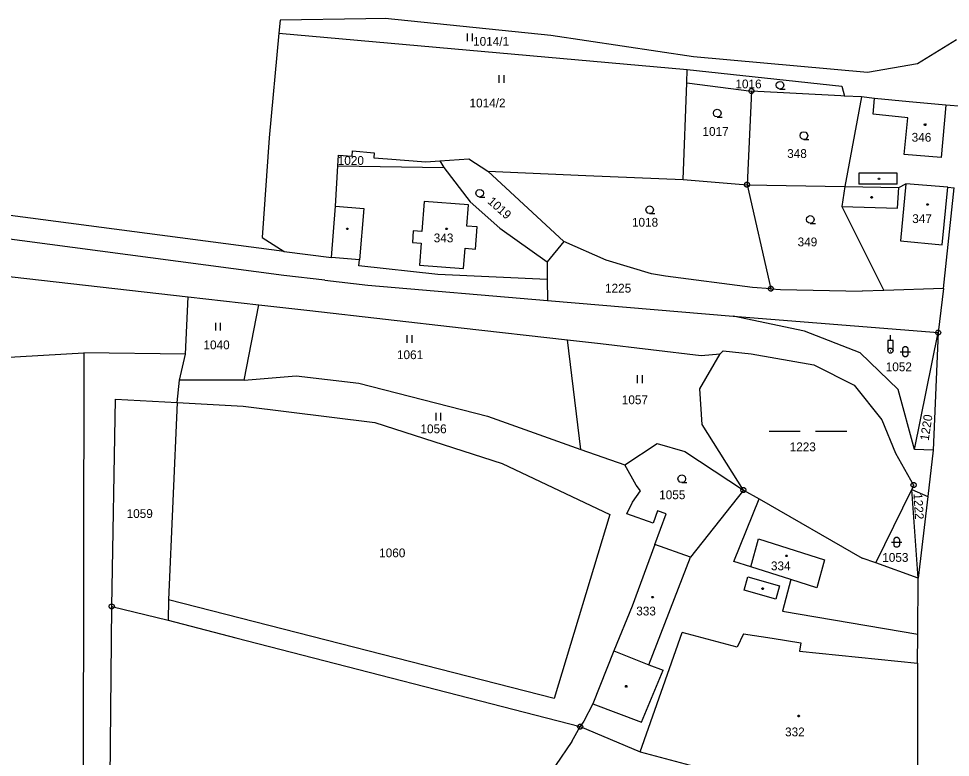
# Model space of a CAD drawing. Extents: x -812394 to -807601, y -1013098 to -1009266.
# Drawn here: x -811185.3 to -811005.4, y -1011290.4 to -1011147.8 of the extents above; entities that cross this region are included whole.
import ezdxf

# ---------------------------------------------------------------- set-up
doc = ezdxf.new("R2010")
doc.units = 0
for name, color, linetype in [('KN_HRANICE', 7, 'Continuous'), ('KN_KULTURY', 7, 'Continuous'), ('KN_MEZNIKY', 7, 'Continuous'), ('KN_PARCELY', 7, 'Continuous'), ('KN_SLUCKY', 7, 'Continuous'), ('KN_VEDENI', 7, 'Continuous')]:
    doc.layers.add(name, color=color, linetype=linetype)

# ---------------------------------------------------------------- blocks, each defined once
blk = doc.blocks.new('304')
blk.add_lwpolyline([(0, 0), (-0.38, 0.1), (-0.65, 0.37), (-0.75, 0.74), (-0.65, 1.11), (-0.38, 1.38), (-0.01, 1.48), (0.36, 1.38), (0.63, 1.11), (0.73, 0.73), (0.63, 0.35), (0.36, 0.08), (-0.02, -0.02), (0.98, -0.02)])
blk = doc.blocks.new('306')
for p, q in [((-0.5, 1.5), (-0.5, 0)), ((0.5, 0), (0.5, 1.5))]:
    blk.add_line(p, q)
blk = doc.blocks.new('316')
for points in [[(-0.5, 1.5), (-0.4, 1.79), (-0.15, 1.97), (0.16, 1.97), (0.41, 1.79), (0.51, 1.5), (0.51, 0.5), (0.41, 0.21), (0.16, 0.03), (-0.15, 0.03), (-0.4, 0.21), (-0.5, 0.5), (-0.5, 1.5)], [(-1, 1), (0.27, 1), (1, 1)]]:
    blk.add_lwpolyline(points)
blk = doc.blocks.new('NAHRADNI_SYMBOL')
blk.add_lwpolyline([(0.09, 0.15), (0.18, 0), (0.09, -0.15), (-0.09, -0.15), (-0.18, 0), (-0.09, 0.15), (0.09, 0.15)])
blk = doc.blocks.new('803')
for p, q in [((-7.5, 0), (-1.5, 0)), ((1.5, 0), (7.5, 0))]:
    blk.add_line(p, q)
blk = doc.blocks.new('402')
blk.add_lwpolyline([(0.09, 0.15), (0.18, 0), (0.09, -0.15), (-0.09, -0.15), (-0.18, 0), (-0.09, 0.15), (0.09, 0.15)])
blk = doc.blocks.new('105')
blk.add_line((-0.12, 0), (0.12, 0))
blk.add_lwpolyline([(0.15, 0.48), (0.4, 0.3), (0.5, 0.01), (0.4, -0.28), (0.15, -0.46), (-0.16, -0.46), (-0.41, -0.28), (-0.51, 0.01), (-0.41, 0.3), (-0.16, 0.48), (0.15, 0.48)])
blk = doc.blocks.new('4112')
for p, q in [((0, 2), (0, 3)), ((-0.05, 0), (0.05, 0))]:
    blk.add_line(p, q)
for points in [[(0.5, 0), (0.4, -0.29), (0.15, -0.47), (-0.16, -0.47), (-0.41, -0.29), (-0.51, 0), (-0.41, 0.29), (-0.16, 0.47), (0.15, 0.47), (0.4, 0.29), (0.5, 0), (0.5, 1.27), (0.5, 2), (0, 2), (-0.5, 2), (-0.5, 0.73), (-0.5, 0)], [(-0.05, 0), (0, 0), (0.05, 0)]]:
    blk.add_lwpolyline(points)

msp = doc.modelspace()

# ---------------------------------------------------------------- linework, layer by layer
at = {"layer": 'KN_HRANICE'}
for p, q in [((-811114.53, -1011147.8), (-811118.29, -1011147.86)), ((-811082.55, -1011151.04), (-811114.53, -1011147.8)), ((-811135.05, -1011150.61), (-811056.18, -1011157.62)), ((-811055, -1011155.17), (-811082.55, -1011151.04)), ((-811004.2, -1011151.86), (-811011.7, -1011156.55)), ((-811021.36, -1011158.23), (-811055, -1011155.17)), ((-811011.7, -1011156.55), (-811021.36, -1011158.23)), ((-811056.28, -1011160.19), (-811056.18, -1011157.62)), ((-811056.99, -1011178.87), (-811056.28, -1011160.19)), ((-811056.28, -1011160.19), (-811043.79, -1011161.8)), ((-811043.79, -1011161.8), (-811044.65, -1011179.88)), ((-811026.5, -1011162.71), (-811043.79, -1011161.8)), ((-811025.83, -1011162.74), (-811026.5, -1011162.71)), ((-811022.54, -1011162.91), (-811025.83, -1011162.74)), ((-811022.54, -1011162.91), (-811025.73, -1011180.21)), ((-811020, -1011163.23), (-811022.54, -1011162.91)), ((-811013.31, -1011163.87), (-811020, -1011163.23)), ((-811006.28, -1011164.5), (-811013.31, -1011163.87)), ((-811002.95, -1011164.79), (-811006.28, -1011164.5)), ((-811124.13, -1011184), (-811123.68, -1011176.2)), ((-811123.68, -1011176.2), (-811103.23, -1011176.54)), ((-811103.94, -1011175.27), (-811098.37, -1011174.88)), ((-811103.94, -1011175.27), (-811103.23, -1011176.54)), ((-811098.37, -1011174.88), (-811094.68, -1011177.27)), ((-811080.02, -1011190.85), (-811094.68, -1011177.27)), ((-811056.99, -1011178.87), (-811044.65, -1011179.88)), ((-811044.65, -1011179.88), (-811025.73, -1011180.21)), ((-811044.65, -1011179.88), (-811040.04, -1011199.96)), ((-811015.31, -1011180.39), (-811013.97, -1011179.67)), ((-811005.89, -1011180.37), (-811013.97, -1011179.67)), ((-811025.73, -1011180.21), (-811026.32, -1011184.09)), ((-811025.73, -1011180.21), (-811015.31, -1011180.39)), ((-811006.73, -1011199.88), (-811004.64, -1011180.47)), ((-811005.89, -1011180.37), (-811004.64, -1011180.47)), ((-811134.04, -1011192.78), (-811204.59, -1011183.52)), ((-811124.88, -1011193.92), (-811124.13, -1011184)), ((-811026.32, -1011184.09), (-811018.25, -1011200.3)), ((-811080.02, -1011190.85), (-811083.26, -1011194.74)), ((-811134.04, -1011192.78), (-811124.88, -1011193.92)), ((-811119.51, -1011194.4), (-811124.88, -1011193.92)), ((-811119.59, -1011195.52), (-811119.51, -1011194.4)), ((-811210.26, -1011194.98), (-811152.56, -1011201.49)), ((-811083.26, -1011194.74), (-811083.23, -1011198.18)), ((-811126.17, -1011198.3), (-811117.85, -1011199.26)), ((-811117.85, -1011199.26), (-811083.19, -1011202.2)), ((-811083.23, -1011198.18), (-811083.19, -1011202.2)), ((-811153.06, -1011212.61), (-811152.56, -1011201.49)), ((-811152.56, -1011201.49), (-811138.94, -1011203.04)), ((-811040.04, -1011199.96), (-811038.15, -1011200.07)), ((-811038.15, -1011200.07), (-811022.4, -1011200.45)), ((-811018.25, -1011200.3), (-811022.4, -1011200.45)), ((-811006.73, -1011199.88), (-811018.25, -1011200.3)), ((-811006.73, -1011199.88), (-811007.74, -1011208.42)), ((-811141.76, -1011217.63), (-811138.94, -1011203.04)), ((-811138.94, -1011203.04), (-811129.08, -1011204.17)), ((-811083.19, -1011202.2), (-811047.34, -1011205.25)), ((-811129.08, -1011204.17), (-811099.83, -1011207.51)), ((-811047.34, -1011205.25), (-811007.74, -1011208.42)), ((-811099.83, -1011207.51), (-811079.29, -1011209.81)), ((-811012.31, -1011230.97), (-811007.74, -1011208.42)), ((-811007.74, -1011208.42), (-811008.72, -1011231.09)), ((-811076.71, -1011230.96), (-811079.29, -1011209.81)), ((-811192.07, -1011213.48), (-811172.71, -1011212.32)), ((-811172.71, -1011212.32), (-811172.89, -1011326.55)), ((-811153.06, -1011212.61), (-811172.71, -1011212.32)), ((-811154.23, -1011217.6), (-811153.06, -1011212.61)), ((-811154.72, -1011221.9), (-811154.23, -1011217.6)), ((-811141.76, -1011217.63), (-811154.23, -1011217.6)), ((-811167.33, -1011261.3), (-811166.6, -1011221.24)), ((-811166.6, -1011221.24), (-811154.72, -1011221.9)), ((-811154.72, -1011221.9), (-811156.36, -1011260.04)), ((-811154.72, -1011221.9), (-811141.93, -1011222.61)), ((-811141.93, -1011222.61), (-811116.52, -1011225.79)), ((-811116.52, -1011225.79), (-811091.96, -1011233.67)), ((-811076.71, -1011230.96), (-811068.27, -1011233.96)), ((-811008.72, -1011231.09), (-811012.31, -1011230.97)), ((-811008.72, -1011231.09), (-811009.72, -1011240.09)), ((-811091.96, -1011233.67), (-811071.16, -1011243.55)), ((-811045.35, -1011238.81), (-811055.55, -1011251.77)), ((-811045.35, -1011238.81), (-811042.32, -1011240.54)), ((-811019.74, -1011252.9), (-811012.81, -1011238.74)), ((-811012.81, -1011238.74), (-811009.72, -1011240.09)), ((-811011.6, -1011255.83), (-811012.81, -1011238.74)), ((-811047.2, -1011252.6), (-811042.32, -1011240.54)), ((-811042.32, -1011240.54), (-811022.4, -1011251.94)), ((-811009.72, -1011240.09), (-811011.6, -1011255.83)), ((-811071.16, -1011243.55), (-811081.9, -1011279.06)), ((-811062.44, -1011249.35), (-811066.83, -1011261.23)), ((-811055.55, -1011251.77), (-811062.44, -1011249.35)), ((-811019.74, -1011252.9), (-811022.4, -1011251.94)), ((-811043.88, -1011253.66), (-811047.2, -1011252.6)), ((-811036.19, -1011256.11), (-811043.88, -1011253.66)), ((-811011.6, -1011255.83), (-811019.74, -1011252.9)), ((-811036.19, -1011256.11), (-811037.78, -1011262.21)), ((-811011.67, -1011266.63), (-811011.6, -1011255.83)), ((-811156.36, -1011260.04), (-811156.44, -1011263.96)), ((-811081.9, -1011279.06), (-811156.36, -1011260.04)), ((-811167.89, -1011326.74), (-811167.33, -1011261.3)), ((-811167.33, -1011261.3), (-811156.44, -1011263.96)), ((-811066.83, -1011261.23), (-811070.36, -1011269.87)), ((-811037.78, -1011262.21), (-811011.67, -1011266.63)), ((-811156.44, -1011263.96), (-811143.37, -1011267.37)), ((-811065.28, -1011289.37), (-811057.2, -1011266.35)), ((-811046.57, -1011269.18), (-811057.2, -1011266.35)), ((-811143.37, -1011267.37), (-811076.86, -1011284.5)), ((-811045.32, -1011266.57), (-811046.57, -1011269.18)), ((-811045.32, -1011266.57), (-811039.78, -1011267.43)), ((-811039.78, -1011267.43), (-811034.25, -1011268.29)), ((-811011.7, -1011272.27), (-811011.67, -1011266.63)), ((-811070.36, -1011269.87), (-811074.4, -1011280.09)), ((-811034.25, -1011268.29), (-811034.51, -1011269.93)), ((-811034.51, -1011269.93), (-811011.7, -1011272.27)), ((-811011.7, -1011272.27), (-811011.75, -1011293.77)), ((-811074.4, -1011280.09), (-811076.18, -1011283.43)), ((-811076.18, -1011283.43), (-811076.86, -1011284.5)), ((-811078.49, -1011287.34), (-811076.86, -1011284.5)), ((-811076.86, -1011284.5), (-811065.28, -1011289.37)), ((-811078.49, -1011287.34), (-811081.65, -1011291.97)), ((-811065.28, -1011289.37), (-811054.65, -1011292.2))]:
    msp.add_line(p, q, dxfattribs=at)
for points in [[(-811118.29, -1011147.86), (-811134.82, -1011148.12), (-811135.05, -1011150.61)], [(-811135.05, -1011150.61), (-811136.91, -1011170.79), (-811138.29, -1011190.03), (-811134.04, -1011192.78)], [(-811056.18, -1011157.62), (-811026.31, -1011160.81), (-811025.83, -1011162.74)], [(-811123.68, -1011176.2), (-811123.56, -1011174.16), (-811120.9, -1011174.34), (-811120.82, -1011173.33), (-811116.66, -1011173.68), (-811116.74, -1011174.67), (-811114.06, -1011174.87), (-811106.69, -1011175.46), (-811103.94, -1011175.27)], [(-811103.23, -1011176.54), (-811098.1, -1011183.16), (-811092.39, -1011188.27), (-811083.26, -1011194.74)], [(-811094.68, -1011177.27), (-811075.76, -1011178.11), (-811056.99, -1011178.87)], [(-811126.17, -1011198.3), (-811134.07, -1011197.39), (-811205.09, -1011188), (-811235.6, -1011185.13), (-811253.42, -1011185.08)], [(-811040.04, -1011199.96), (-811043.56, -1011199.74), (-811060.37, -1011197.53), (-811063.11, -1011197.07), (-811071.87, -1011194.45), (-811080.02, -1011190.85)], [(-811083.23, -1011198.18), (-811104.34, -1011197.21), (-811119.59, -1011195.52)], [(-811012.31, -1011230.97), (-811015.45, -1011219.39), (-811022.8, -1011212.32), (-811033.57, -1011208.12), (-811047.34, -1011205.25)], [(-811079.29, -1011209.81), (-811072.96, -1011210.52), (-811053.49, -1011212.84), (-811049.84, -1011212.52)], [(-811049.84, -1011212.52), (-811049.25, -1011211.91), (-811043.85, -1011212.49), (-811031.77, -1011214.67), (-811023.94, -1011218.57), (-811018.6, -1011225.28), (-811016, -1011231.72), (-811012.47, -1011237.86), (-811012.81, -1011238.74)], [(-811045.35, -1011238.81), (-811053.28, -1011226.18), (-811053.74, -1011219.25), (-811049.84, -1011212.52)], [(-811141.76, -1011217.63), (-811131.69, -1011216.74), (-811119.6, -1011218.21), (-811094.76, -1011224.53), (-811076.71, -1011230.96)], [(-811068.27, -1011233.96), (-811061.97, -1011229.86), (-811056.63, -1011231.35), (-811045.35, -1011238.81)], [(-811062.44, -1011249.35), (-811060.27, -1011243.4), (-811061.93, -1011242.85), (-811062.75, -1011245.19), (-811067.83, -1011243.42), (-811066.75, -1011241.18), (-811065.25, -1011238.95), (-811066.04, -1011237.88), (-811068.27, -1011233.96)]]:
    msp.add_lwpolyline(points, dxfattribs=at)
at = {"layer": 'KN_SLUCKY'}
for p, q in [((-811020.31, -1011166.25), (-811020, -1011163.23)), ((-811006.28, -1011164.5), (-811007.17, -1011174.62)), ((-811013.57, -1011166.94), (-811020.31, -1011166.25)), ((-811014.3, -1011174.03), (-811013.57, -1011166.94)), ((-811007.17, -1011174.62), (-811014.3, -1011174.03)), ((-811015.68, -1011177.63), (-811023.04, -1011177.63)), ((-811023.04, -1011177.63), (-811023.04, -1011179.74)), ((-811015.68, -1011179.74), (-811015.68, -1011177.63)), ((-811015.68, -1011179.74), (-811023.04, -1011179.74)), ((-811013.97, -1011179.67), (-811015.01, -1011190.72)), ((-811015.57, -1011184.38), (-811015.31, -1011180.39)), ((-811006.98, -1011191.46), (-811005.89, -1011180.37)), ((-811026.32, -1011184.09), (-811015.57, -1011184.38)), ((-811015.01, -1011190.72), (-811006.98, -1011191.46)), ((-811043.88, -1011253.66), (-811042.43, -1011248.25)), ((-811042.43, -1011248.25), (-811029.67, -1011252.31)), ((-811063.58, -1011272.55), (-811055.55, -1011251.77)), ((-811029.67, -1011252.31), (-811031.16, -1011257.72)), ((-811045.19, -1011258.17), (-811044.48, -1011255.6)), ((-811044.48, -1011255.6), (-811038.35, -1011257.29)), ((-811038.35, -1011257.29), (-811039.06, -1011259.86)), ((-811031.16, -1011257.72), (-811036.19, -1011256.11)), ((-811039.06, -1011259.86), (-811045.19, -1011258.17)), ((-811070.36, -1011269.87), (-811063.58, -1011272.55)), ((-811065.03, -1011283.62), (-811060.86, -1011273.62)), ((-811063.58, -1011272.55), (-811060.86, -1011273.62)), ((-811074.4, -1011280.09), (-811065.03, -1011283.62))]:
    msp.add_line(p, q, dxfattribs=at)
msp.add_lwpolyline([(-811107.44, -1011188.88), (-811109.09, -1011188.75), (-811109.27, -1011191.03), (-811107.56, -1011191.17), (-811107.89, -1011195.41), (-811099.4, -1011196.06), (-811099.09, -1011192.13), (-811097.08, -1011192.29), (-811096.74, -1011188.01), (-811098.74, -1011187.86), (-811098.41, -1011183.73), (-811106.99, -1011183.09)], close=True, dxfattribs=at)
msp.add_lwpolyline([(-811124.13, -1011184), (-811118.64, -1011184.45), (-811119.51, -1011194.4)], dxfattribs=at)

# ---------------------------------------------------------------- block references
at = {"layer": 'KN_KULTURY'}
for name, p in [('306', (-811098.18, -1011152.15)), ('306', (-811092.05, -1011160.21)), ('304', (-811038.28, -1011161.4)), ('304', (-811050.4, -1011166.78)), ('402', (-811010.26, -1011168.29)), ('304', (-811033.66, -1011171.12)), ('402', (-811019.17, -1011178.74)), ('304', (-811096.26, -1011182.24)), ('402', (-811020.57, -1011182.29)), ('402', (-811009.78, -1011183.68)), ('304', (-811063.44, -1011185.43)), ('304', (-811032.42, -1011187.31)), ('402', (-811121.83, -1011188.38)), ('402', (-811102.67, -1011188.38)), ('306', (-811146.8, -1011208.03)), ('306', (-811109.84, -1011210.39)), ('316', (-811014.08, -1011213.1)), ('306', (-811065.35, -1011218.16)), ('306', (-811104.25, -1011225.42)), ('803', (-811032.89, -1011227.45)), ('304', (-811057.24, -1011237.37)), ('316', (-811015.74, -1011249.9)), ('402', (-811037.02, -1011251.51)), ('402', (-811041.63, -1011257.85)), ('402', (-811062.89, -1011259.49)), ('402', (-811067.98, -1011276.71)), ('NAHRADNI_SYMBOL', (-811034.67, -1011282.44))]:
    msp.add_blockref(name, p, dxfattribs=at)
at = {"layer": 'KN_MEZNIKY'}
for p in [(-811043.79, -1011161.8), (-811044.65, -1011179.88), (-811040.04, -1011199.96), (-811007.74, -1011208.42), (-811012.47, -1011237.86), (-811045.35, -1011238.81), (-811167.33, -1011261.3), (-811076.86, -1011284.5)]:
    msp.add_blockref('105', p, dxfattribs=at)
at = {"layer": 'KN_VEDENI'}
msp.add_blockref('4112', (-811016.94, -1011211.92), dxfattribs=at)

# ---------------------------------------------------------------- texts
at = {"layer": 'KN_PARCELY'}
for s, p in [('1014/1', (-811097.55, -1011153.04)), ('1016', (-811046.89, -1011161.26)), ('1014/2', (-811098.24, -1011164.94)), ('1017', (-811053.25, -1011170.43)), ('346', (-811012.85, -1011171.56)), ('1020', (-811123.69, -1011176.04)), ('348', (-811036.89, -1011174.7)), ('1018', (-811066.87, -1011187.97)), ('347', (-811012.74, -1011187.27)), ('343', (-811105.15, -1011190.99)), ('349', (-811034.88, -1011191.76)), ('1225', (-811072.07, -1011200.69)), ('1040', (-811149.62, -1011211.64)), ('1061', (-811112.25, -1011213.54)), ('1052', (-811017.86, -1011215.88)), ('1057', (-811068.83, -1011222.24)), ('1056', (-811107.71, -1011227.85)), ('1223', (-811036.41, -1011231.33)), ('1055', (-811061.61, -1011240.58)), ('1059', (-811164.46, -1011244.21)), ('1060', (-811115.69, -1011251.8)), ('1053', (-811018.53, -1011252.68)), ('334', (-811040.03, -1011254.31)), ('333', (-811066.04, -1011263.03)), ('332', (-811037.3, -1011286.37))]:
    msp.add_text(s, height=1.7, dxfattribs=at).set_placement(p)
for s, rotation, p in [('1019', 318.106, (-811094.88, -1011183.29)), ('1220', 81.36, (-811009.57, -1011229.37)), ('1222', 273.645, (-811012.5, -1011239.5))]:
    msp.add_text(s, height=1.7, rotation=rotation, dxfattribs=at).set_placement(p)

doc.saveas('drawing.dxf')
